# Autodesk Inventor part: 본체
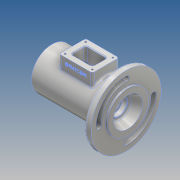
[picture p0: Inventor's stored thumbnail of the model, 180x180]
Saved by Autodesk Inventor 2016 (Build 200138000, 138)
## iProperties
Created: 2017-05
Part Number: 본체
Material: 알루미늄 6061
Document SubType Name: Modeling
Designer: Administrator
Mass: 680.072 g
Surface Area: 618.647 cm^2
Volume: 251.879 cm^3
Density: 2.7 g/cm^3
Appearance: 알루미늄 - 평지
Author: Administrator
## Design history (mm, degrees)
sketch "스케치1"
  geometry: L1 (57.5, 0)-(-57.5, 0); L2 (57.5, 0)-(57.5, 31); L3 (57.5, 31)-(-44.5, 31); L4 (-54.5, 31)-(-54.5, 53); L5 (-54.5, 53)-(-44.5, 53); L6 (-44.5, 53)-(-44.5, 31); L7 (-54.5, 31)-(-57.5, 31); L8 (-57.5, 31)-(-57.5, 0); 2 further points
  constraints: 16 end point, 5 perpendicular, 1 coincident, 1 horizontal, 1 midpoint, 1 point on line, 1 vertical
  dimensions: "d0" = 115 distance between parallel lines of L8 L2; "d2" = 62 diameter of L3 L1; "d4" = 13 distance between parallel lines of L8 L6; "d5" = 3 distance between parallel lines of L8 L4; "d6" = 106 diameter of L5 L1
revolve "회전1" sketch "스케치1" stored, may be unused: angle "d7" = 90 deg
sketch "스케치3"
  geometry: L1 (-57.5, 31)-(-57.5, -31) reference; L2 (57.5, 31)-(57.5, -31) reference; L3 (44.5, 31)-(-57.5, 31) reference; L4 (-26.5, -20)-(23.5, -20); L5 (23.5, -20)-(23.5, 20); L6 (23.5, 20)-(-26.5, 20); L7 (-26.5, 20)-(-26.5, -20); L8 (-26.5, -20)-(23.5, 20); L9 (23.5, -20)-(-26.5, 20); 3 further points
  constraints: 12 end point, 3 midpoint, 2 parallel, 1 horizontal, 1 horizontal alignment, 1 perpendicular
  dimensions: "d35" = 56 distance from line of point (-1.5, 0) L1; "d36" = 50 distance between parallel lines of L5 L7; "d37" = 40 distance between parallel lines of L4 L6
extrude "돌출1" join sketch "스케치3" distance "d38" = 44; taper "d39" = 0 deg
sketch "스케치2"
  geometry: L1 (57.5, 0)-(-57.5, 0); L2 (57.5, -31)-(57.5, 31) reference; L3 (-57.5, -31)-(-57.5, 31) reference; L4 (48.5, 0)-(48.5, 24); L5 (48.5, 24)-(45.5, 24); L6 (45.5, 24)-(45.5, 20); L7 (45.5, 20)-(36.5, 20); L8 (36.5, 20)-(36.5, 17.5); L9 (36.5, 17.5)-(33.25, 17.5); L10 (33.25, 17.5)-(33.25, 18.5); L11 (33.25, 18.5)-(31.5, 18.5); L12 (31.5, 18.5)-(31.5, 17.5); L13 (31.5, 17.5)-(20.5, 17.5); L14 (20.5, 17.5)-(20.5, 26); L15 (20.5, 26)-(-17.5, 26); L16 (-17.5, 26)-(-17.5, 17.5); L17 (-17.5, 17.5)-(-28.5, 17.5); L18 (-28.5, 17.5)-(-28.5, 16.5); L19 (-28.5, 16.5)-(-33.5, 16.5); L20 (-33.5, 16.5)-(-33.5, 10); L21 (-33.5, 10)-(-36.2, 10); L22 (-36.2, 10)-(-36.2, 12.5); L23 (-36.2, 12.5)-(-42.8, 12.5); L24 (-42.8, 12.5)-(-43.5, 12.904); L25 (-43.5, 12.904)-(-43.5, 16); L26 (-43.5, 16)-(-57.5, 22); 4 further points
  constraints: 48 end point, 15 perpendicular, 6 point on line, 5 midpoint, 3 vertical, 2 horizontal, 1 coincident
  dimensions: "d9" = 12 distance between parallel lines of L6 L2; "d10" = 3 distance between parallel lines of L6 L4; "d11" = 21 distance between parallel lines of L8 L2; "d12" = 26 distance between parallel lines of L12 L2; "d13" = 60 distance between parallel lines of L18 L12; "d14" = 38 distance between parallel lines of L16 L14; "d15" = 5 distance between parallel lines of L20 L18; "d16" = 14 distance from line of L3 L24.end; "d17" = 1.75 distance between parallel lines of L12 L10; "d18" = 48 diameter of L5 L1; "d19" = 40 diameter of L7 L1; "d20" = 35 diameter of L13 L1; "d21" = 37 diameter of L11 L1; "d22" = 52 diameter of L15 L1; "d23" = 33 diameter of L19 L1; "d27" = 44 diameter of L26.end L1; "d28" = 30 deg angle of L23 L24; "d29" = 32 diameter of L25.end L1; "d30" = 20 diameter of L21 L1; "d31" = 25 diameter of L23 L1; "d32" = 7.3 distance from line of L22 L24.end; "d33" = 0.7 horizontal distance of L24.end L23.end; "d40" = 56 distance from line of point (1.5, 26) L2
revolve "회전2" sketch "스케치2" stored, may be unused: angle "d34" = 90 deg
fillet "모깎기1" dims "d41" = 3
fillet "모깎기2" dims "d42" = 0.3
sketch "스케치4"
  geometry: L1 (-26.5, 20)-(-26.5, -20) reference; L2 (-17.5, -11)-(14.5, -11); L3 (14.5, -11)-(14.5, 11); L4 (14.5, 11)-(-17.5, 11); L5 (-17.5, 11)-(-17.5, -11); L6 (-17.5, -11)-(14.5, 11); L7 (14.5, -11)-(-17.5, 11); L8 (-57.5, 31)-(-57.5, -31) reference; 3 further points
  constraints: 12 end point, 3 midpoint, 2 parallel, 1 horizontal, 1 horizontal alignment, 1 perpendicular
  dimensions: "d43" = 56 distance from line of point (-1.5, 0) L8; "d44" = 32 distance between parallel lines of L3 L5; "d45" = 22 distance between parallel lines of L2 L4
extrude "돌출2" cut sketch "스케치4" distance "d46" = 44; taper "d47" = 0 deg
hole "구멍1" diameter "d50" = 40.376; stored, may be unused: countersink angle "d54" = 90 deg, drill point angle "d56" = 118 deg; dims "d48" = 10, "d49" = 10, "d51" = 84, "d52" = 4, "d53" = 2, "d55" = 9
sketch "스케치5"
  geometry: L1 (-22, 15.5)-(19, 15.5); L2 (19, 15.5)-(19, -15.5); L3 (19, -15.5)-(-22, -15.5); L4 (-22, -15.5)-(-22, 15.5); L5 (-22, 15.5)-(19, -15.5); L6 (19, 15.5)-(-22, -15.5); L7 (-57.5, 31)-(-57.5, -31) reference; 7 further points
  constraints: 12 end point, 4 coincident, 3 midpoint, 2 parallel, 1 horizontal, 1 horizontal alignment, 1 perpendicular
  dimensions: "d57" = 56 distance from line of L7 point (-1.5, 0); "d58" = 41 distance between parallel lines of L2 L4; "d59" = 31 distance between parallel lines of L3 L1
hole "구멍2" sketch "스케치5" at (-22, 15.5), (-22, -15.5), (19, -15.5), (19, 15.5) diameter "d60" = 2.459; stored, may be unused: countersink angle "d64" = 90 deg, drill point angle "d66" = 118 deg; dims "d61" = 6, "d62" = 4, "d63" = 2, "d65" = 8
chamfer "모따기1" distance "d67" = 1; stored, may be unused: second distance "d68" = 2, angle "d69" = 45 deg
fillet "모깎기3" dims "d70" = 3
fillet "모깎기4" dims "d71" = 3
fillet "모깎기5" dims "d72" = 3
chamfer "모따기2" distance "d73" = 1; stored, may be unused: second distance "d74" = 2, angle "d75" = 45 deg
fillet "모깎기6" dims "d76" = 3
sketch "스케치6"
  geometry: L1 (0, -60.51)-(0, 60.51); L2 (-63.255, 0)-(63.255, 0); C1 r 53 at (0, 0) reference; C2 r 31 at (0, 0) reference; A1 r 41.5 centre (0, 0) between (0, 41.5) and (41.5, 0); A2 r 4 centre (0, 41.5) between (0, 45.5) and (0, 37.5); A3 r 4 centre (41.5, 0) between (37.5, 0) and (45.5, 0); A4 r 4 centre (0, -41.5) between (0, -45.5) and (0, -37.5); A5 r 4 centre (-41.5, 0) between (-37.5, 0) and (-45.5, 0); A6 r 45.5 centre (0, 0) between (-45.5, 0) and (0, -45.5); A7 r 45.5 centre (0, 0) between (45.5, 0) and (0, 45.5); A8 r 37.5 centre (0, 0) between (-37.5, 0) and (0, -37.5); A9 r 37.5 centre (0, 0) between (37.5, 0) and (0, 37.5); 1 further point
  constraints: 20 point on circle, 9 centre point, 4 coincident, 4 end point, 4 point on line, 2 midpoint, 1 horizontal, 1 vertical
  dimensions: "d77" = 83 diameter of A1; "d78" = 8 diameter of A2; "d79" = 8 diameter of A3; "d80" = 8 diameter of A4; "d81" = 8 diameter of A5; "d84" = 37.5 radius of A8; "d85" = 45.5 radius of A6; "d86" = 37.5 radius of A9; "d87" = 45.5 radius of A7
extrude "돌출3" cut sketch "스케치6" distance "d88" = 20; taper "d89" = 0 deg
sketch "스케치7"
  geometry: L1 (0, 0)-(44, 0) reference; L2 (-34, -13)-(-34, -75) reference; 2 further points
  constraints: 1 other
  dimensions: "d90" = 56 distance from line of point (22, -8) L2; "d91" = 8 distance from line of point (22, -8) L1
feature "엠보싱1" sketch "스케치7" dims "d0" = 115, "d2" = 62, "d4" = 13, "d5" = 3, "d6" = 106, "d92" = 0.5, "d93" = 0
node "솔리드1"
other parameters: "d82" = 91, "d83" = 75
